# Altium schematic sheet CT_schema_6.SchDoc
size 581 x 363 mm
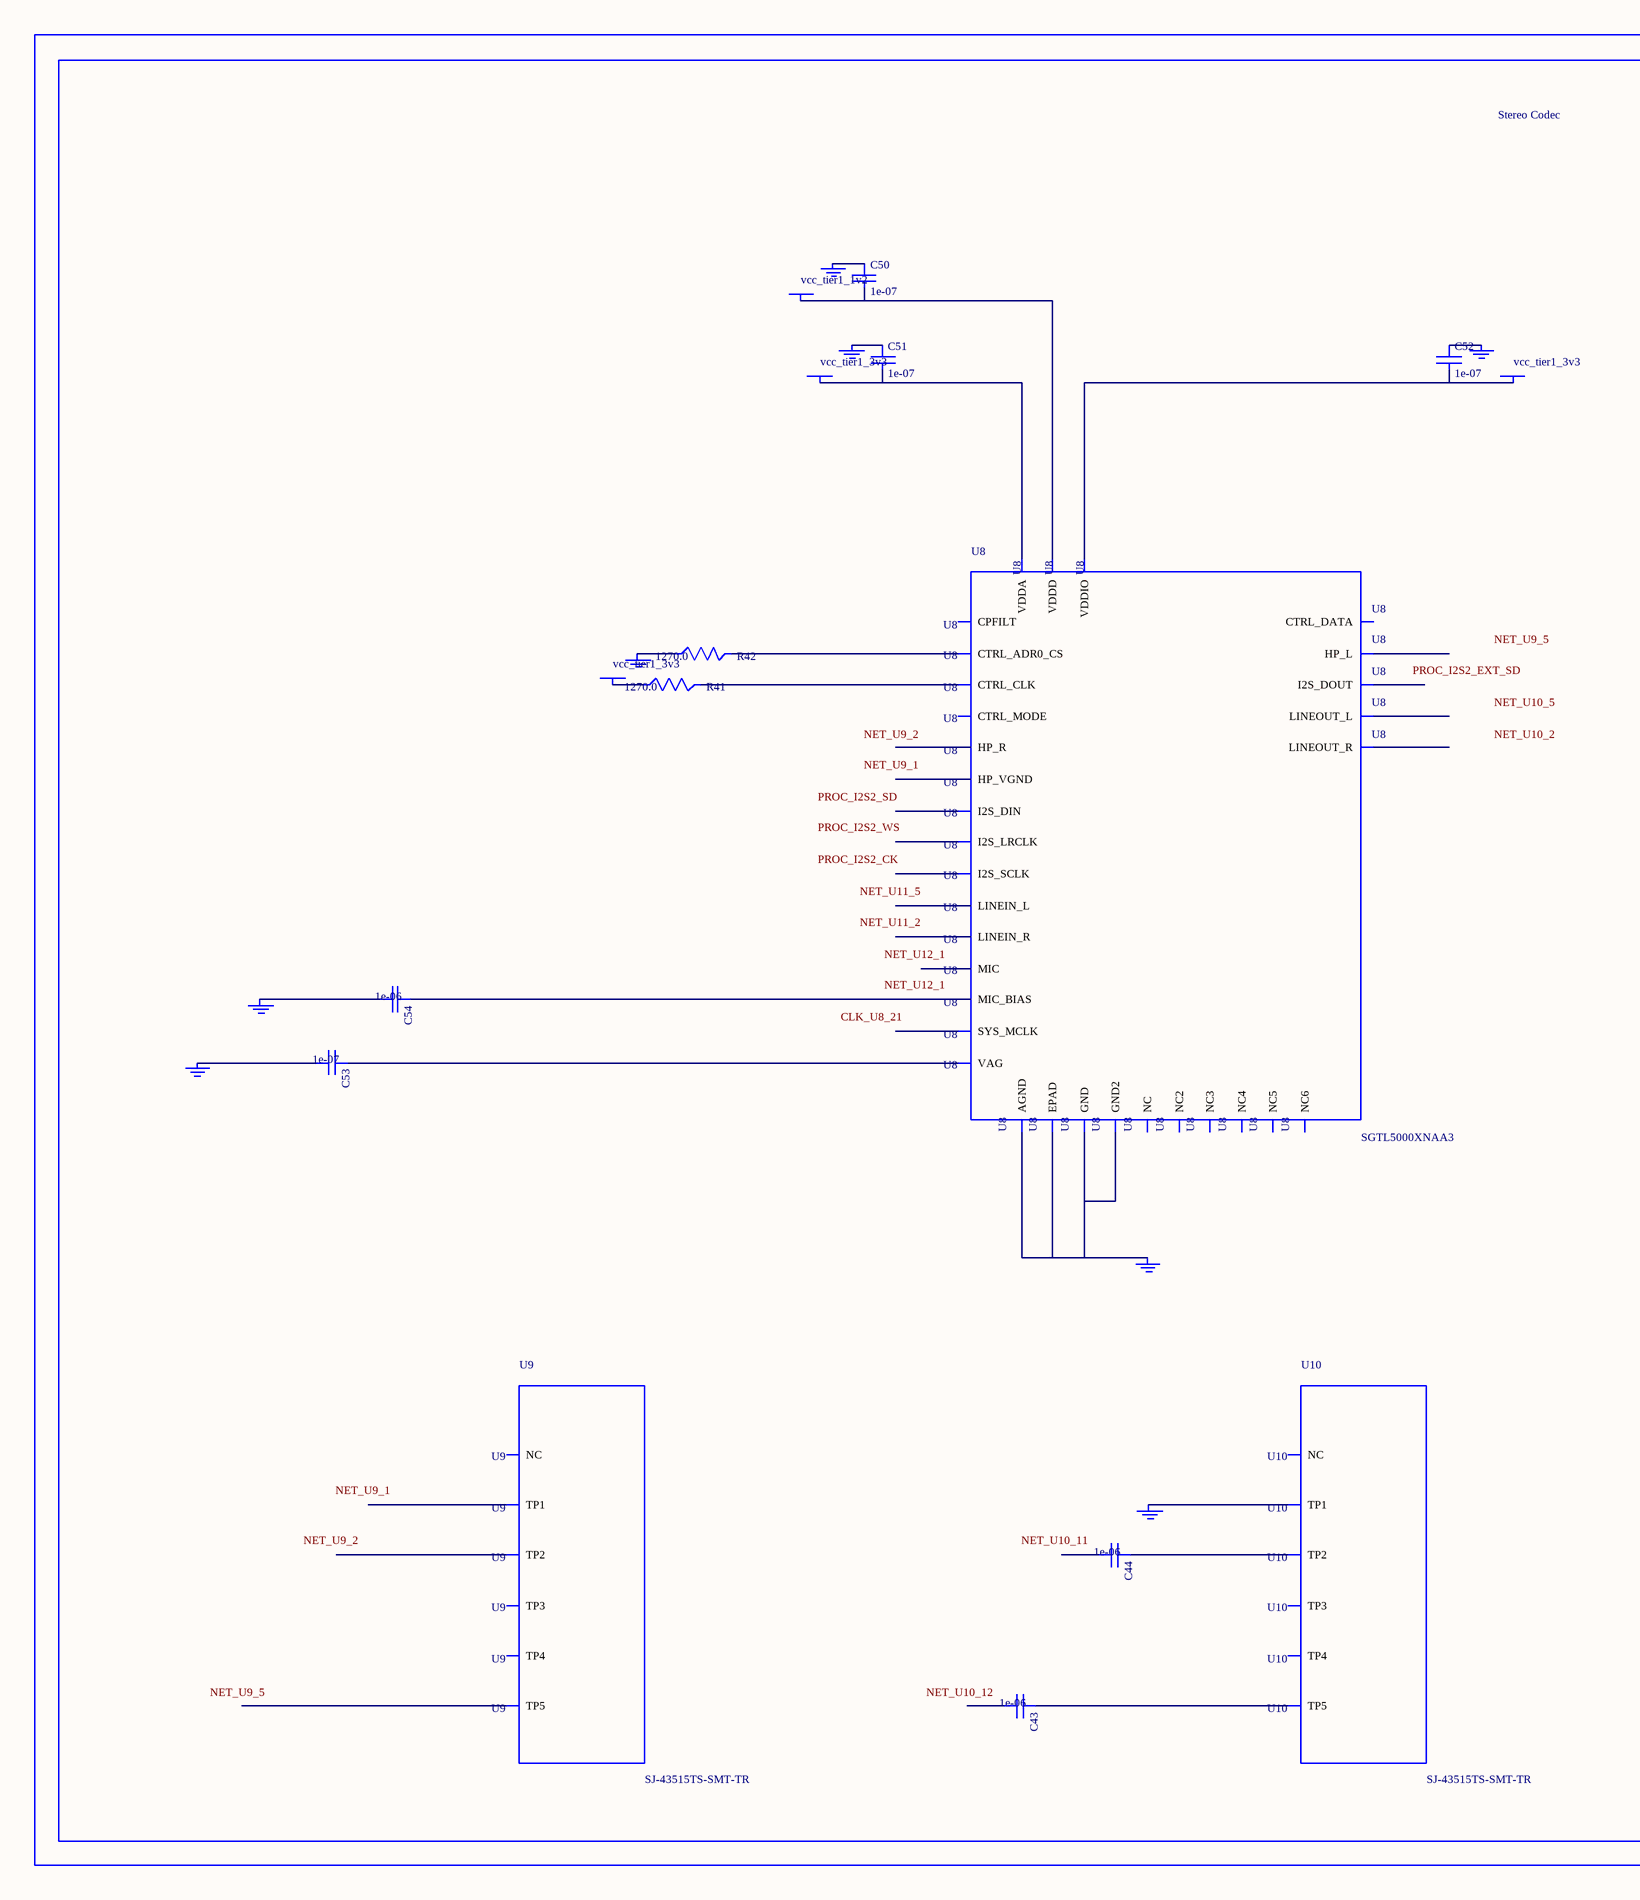
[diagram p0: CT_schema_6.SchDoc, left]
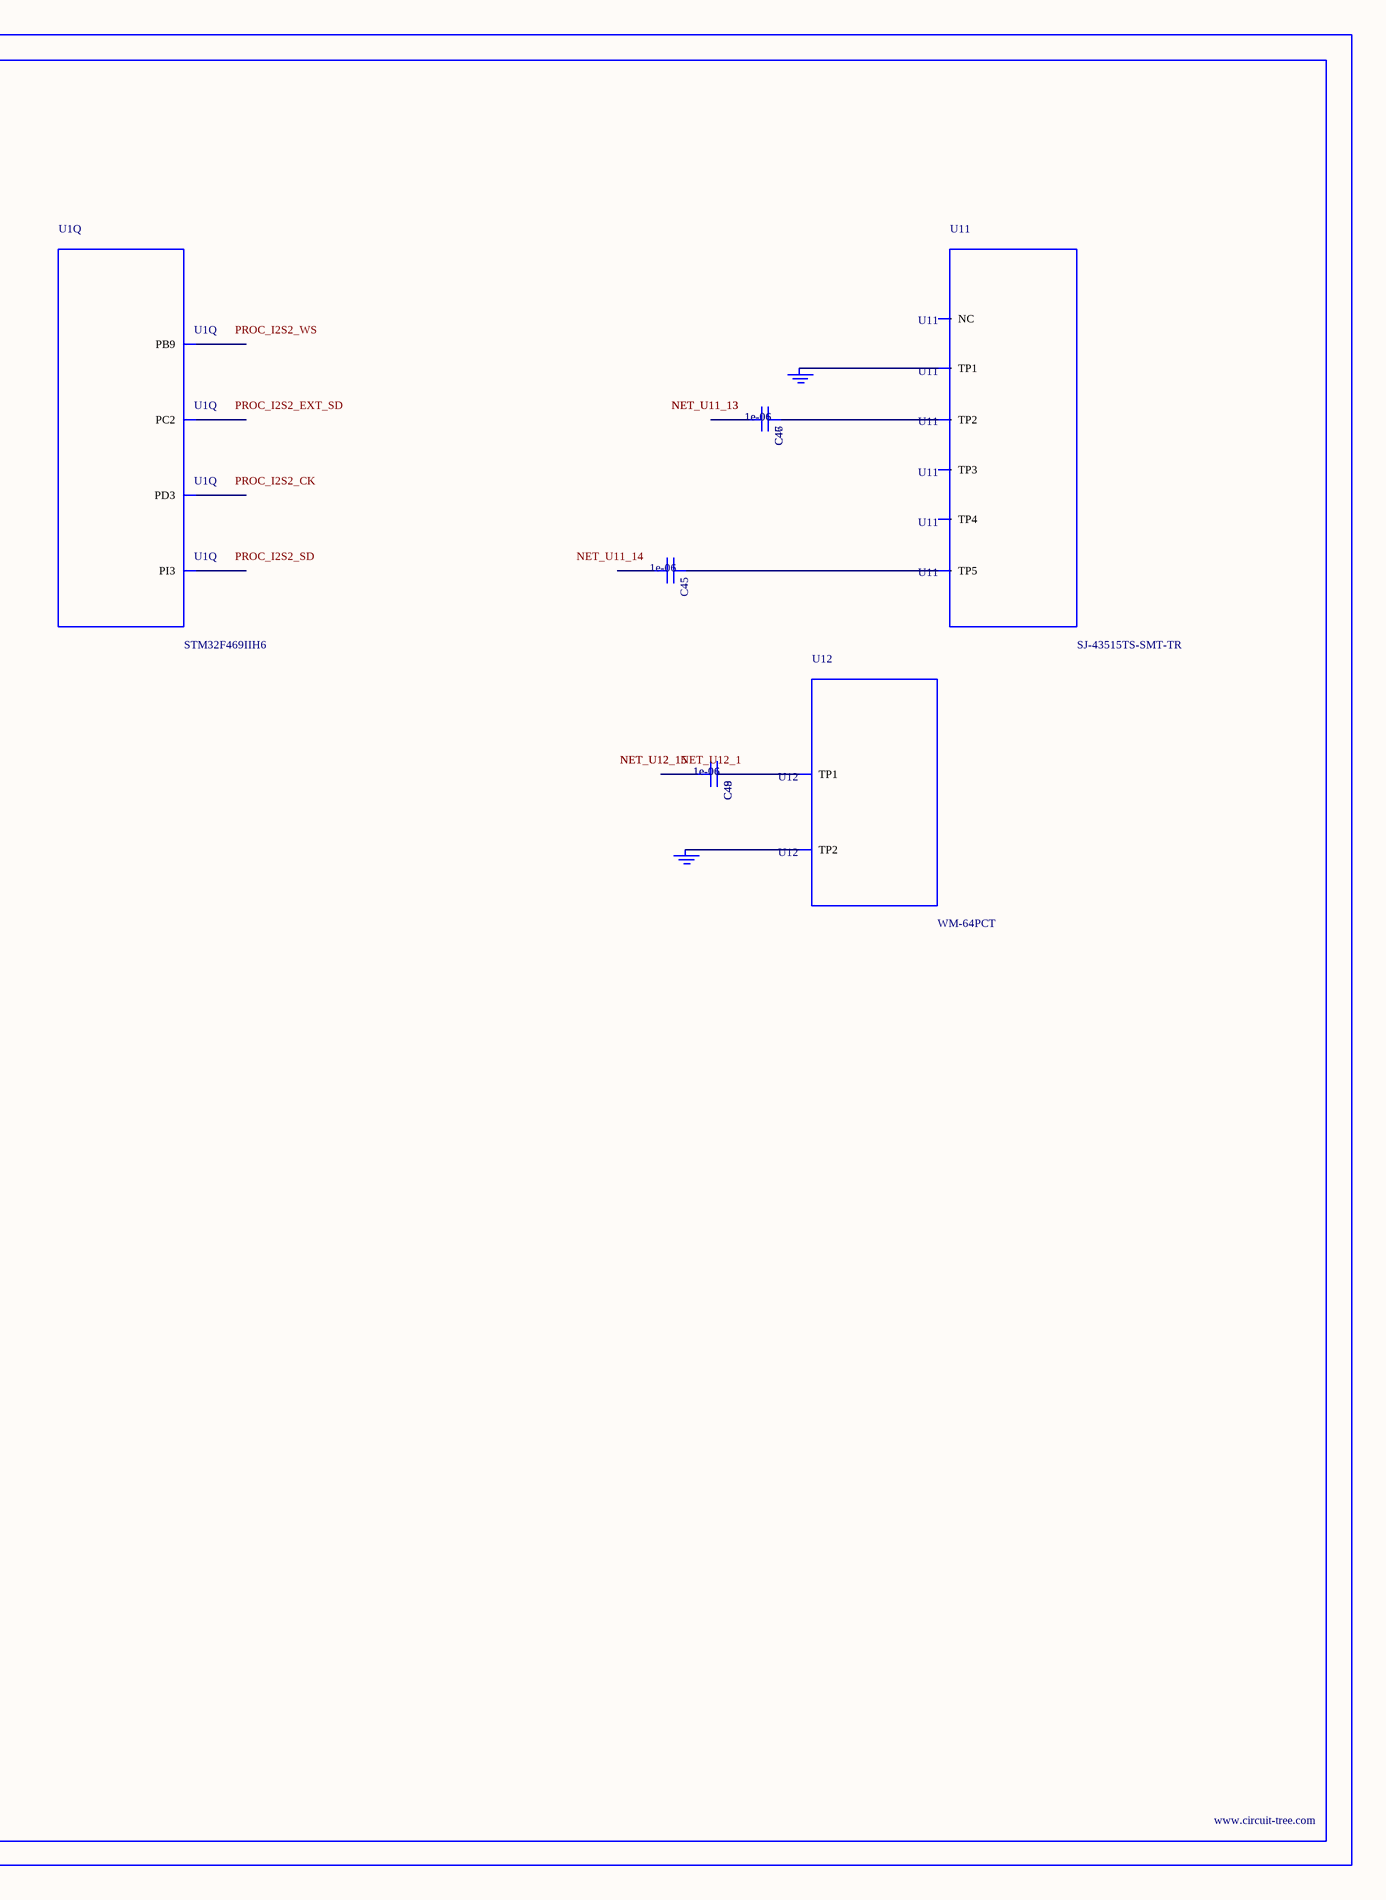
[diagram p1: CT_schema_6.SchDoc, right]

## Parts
BORDER5  (no value)
C43  1e-06  [C0603]
C44  1e-06  [C0603]
C45  1e-06  [C0603]
C46  1e-06  [C0603]
C47  1e-06  [C0603]
C48  1e-06  [C0603]
C49  1e-06  [C0603]
C50  1e-07  [C0402]
C51  1e-07  [C0402]
C52  1e-07  [C0402]
C53  1e-07  [C0402]
C54  1e-06  [C0603]
GND_INSTANCE_5_0  (no value)
GND_INSTANCE_5_1  (no value)
GND_INSTANCE_5_2  (no value)
GND_INSTANCE_5_3  (no value)
GND_INSTANCE_5_4  (no value)
GND_INSTANCE_5_5  (no value)
GND_INSTANCE_5_6  (no value)
GND_INSTANCE_5_7  (no value)
GND_INSTANCE_5_8  (no value)
GND_INSTANCE_5_9  (no value)
GND_INSTANCE_5_10  (no value)
POWER_INSTANCE_5_0  vcc_tier1_3v3
POWER_INSTANCE_5_1  vcc_tier1_3v3
POWER_INSTANCE_5_2  vcc_tier1_3v3
POWER_INSTANCE_5_3  vcc_tier1_1v2
R41  1270.0  [R0603]
R42  1270.0  [R0603]
U1  STM32F469IIH6  [UFBGA176]  (part Q of 17)
U8  SGTL5000XNAA3  [QFN-32]
U9  SJ-43515TS-SMT-TR  [SJ-43515TS-SMT-TR]
U10  SJ-43515TS-SMT-TR  [SJ-43515TS-SMT-TR]
U11  SJ-43515TS-SMT-TR  [SJ-43515TS-SMT-TR]
U12  WM-64PCT  [WM-64PC]

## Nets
NetC43_1: C43.1 U10.5(TP5)
NetC44_1: C44.1 U10.2(TP2)
NetC45_1: C45.1 U11.5(TP5)
NetC46_1: C46.1 C47.1 U11.2(TP2)
NetC46_2: C46.2 C47.2
NetC48_1: C48.1 C49.1 U12.1(TP1)
NetC48_2: C48.2 C49.2
NetC50_1: C50.1 GND_INSTANCE_5_5.0(GND)
NetC50_2: C50.2 POWER_INSTANCE_5_3.0(PWR) U8.30(VDDD)
NetC51_1: C51.1 GND_INSTANCE_5_1.0(GND)
NetC51_2: C51.2 POWER_INSTANCE_5_0.0(PWR) U8.5(VDDA)
NetC52_1: C52.1 GND_INSTANCE_5_4.0(GND)
NetC52_2: C52.2 POWER_INSTANCE_5_1.0(PWR) U8.20(VDDIO)
NetC53_1: C53.1 U8.10(VAG)
NetC53_2: C53.2 GND_INSTANCE_5_2.0(GND)
NetC54_1: C54.1 U8.16(MIC_BIAS)
NetC54_2: C54.2 GND_INSTANCE_5_3.0(GND)
NetGND_INSTANCE_5_0_0: GND_INSTANCE_5_0.0(GND) U8.1(GND) U8.3(GND2) U8.7(AGND) U8.EXP(EPAD)
NetGND_INSTANCE_5_6_0: GND_INSTANCE_5_6.0(GND) R42.1
NetGND_INSTANCE_5_7_0: GND_INSTANCE_5_7.0(GND) U10.1(TP1)
NetGND_INSTANCE_5_8_0: GND_INSTANCE_5_8.0(GND) GND_INSTANCE_5_9.0(GND) U11.1(TP1)
NetGND_INSTANCE_5_10_0: GND_INSTANCE_5_10.0(GND) U12.2(TP2)
NetPOWER_INSTANCE_5_2_0: POWER_INSTANCE_5_2.0(PWR) R41.1
NetR41_2: R41.2 U8.29(CTRL_CLK)
NetR42_2: R42.2 U8.31(CTRL_ADR0_CS)

Not connected (* = marked no-connect by the designer): C43 2; C44 2; C45 2; U1 B4(PB9) C13(PI3) D11(PD3) M4(PC2); U8 2(HP_R) 4(HP_VGND) 6(HP_L) 8(NC) 9(NC2) 11(LINEOUT_R) 12(LINEOUT_L) 13(LINEIN_R) 14(LINEIN_L) 15(MIC) 17(NC3) 18(CPFILT) 19(NC4) 21(SYS_MCLK) 22(NC5) 23(I2S_LRCLK) 24(I2S_SCLK) 25(I2S_DOUT) 26(I2S_DIN) 27(CTRL_DATA) 28(NC6) 32(CTRL_MODE); U9 1(TP1) 2(TP2) 3(TP3) 4(TP4) 5(TP5) 6(NC); U10 3(TP3) 4(TP4) 6(NC); U11 3(TP3) 4(TP4) 6(NC)

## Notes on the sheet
- Labels drawn without touching a wire or pin: CLK_U8_21, NET_U9_1, NET_U9_2, NET_U9_5, NET_U10_2, NET_U10_5, NET_U10_11, NET_U10_12, NET_U11_2, NET_U11_5, NET_U11_14, NET_U12_1, PROC_I2S2_CK, PROC_I2S2_EXT_SD, PROC_I2S2_SD, PROC_I2S2_WS

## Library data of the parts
BORDER5 = BORDER_PAGE5
C43-C49 C54 = C0603C105K3RACTU
C50-C53 = C0402C104K3RACTU
GND_INSTANCE_5_0-GND_INSTANCE_5_10 = GND
POWER_INSTANCE_5_0-POWER_INSTANCE_5_3 = PWR
R41 R42 = RC0603FR-071K27L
